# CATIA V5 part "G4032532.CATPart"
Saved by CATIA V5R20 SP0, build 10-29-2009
Part number: G4032532
Revision: 3
Definition: design
Nomenclature: G4032532
Source: made
Description: NOT SPECIFIED
Bounding box of the stored display mesh (mm): x -16 to 16, y -18.807 to 18.807, z -19 to 19
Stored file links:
  C:\Users\Raffaele\Desktop\3D X SITO CF\BOLEX\27-BUSH REF 403\G4032532.CATPart
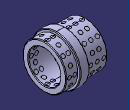
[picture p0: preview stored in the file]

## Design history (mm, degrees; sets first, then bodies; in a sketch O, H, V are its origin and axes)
Body1 "MANIFOLD_SOLID_BREP #9169" (main body)
  Solid1: solid without history
Body2 "MANIFOLD_SOLID_BREP #9312"
  Solid2: solid without history
Body3 "MANIFOLD_SOLID_BREP #9455"
  Solid3: solid without history
Body4 "MANIFOLD_SOLID_BREP #9598"
  Solid4: solid without history
Body5 "MANIFOLD_SOLID_BREP #9741"
  Solid5: solid without history
Body6 "MANIFOLD_SOLID_BREP #9886"
  Solid6: solid without history
Body7 "MANIFOLD_SOLID_BREP #10031"
  Solid7: solid without history
Body8 "MANIFOLD_SOLID_BREP #10176"
  Solid8: solid without history
Body9 "MANIFOLD_SOLID_BREP #10321"
  Solid9: solid without history
Body10 "MANIFOLD_SOLID_BREP #10466"
  Solid10: solid without history
Body11 "MANIFOLD_SOLID_BREP #10611"
  Solid11: solid without history
Body12 "MANIFOLD_SOLID_BREP #10756"
  Solid12: solid without history
Body13 "MANIFOLD_SOLID_BREP #10901"
  Solid13: solid without history
Body14 "MANIFOLD_SOLID_BREP #11046"
  Solid14: solid without history
Body15 "MANIFOLD_SOLID_BREP #11191"
  Solid15: solid without history
Body16 "MANIFOLD_SOLID_BREP #11336"
  Solid16: solid without history
Body17 "MANIFOLD_SOLID_BREP #11481"
  Solid17: solid without history
Body18 "MANIFOLD_SOLID_BREP #11626"
  Solid18: solid without history
Body19 "MANIFOLD_SOLID_BREP #11771"
  Solid19: solid without history
Body20 "MANIFOLD_SOLID_BREP #11916"
  Solid20: solid without history
Body21 "MANIFOLD_SOLID_BREP #12061"
  Solid21: solid without history
Body22 "MANIFOLD_SOLID_BREP #12206"
  Solid22: solid without history
Body23 "MANIFOLD_SOLID_BREP #12351"
  Solid23: solid without history
Body24 "MANIFOLD_SOLID_BREP #12496"
  Solid24: solid without history
Body25 "MANIFOLD_SOLID_BREP #12641"
  Solid25: solid without history
Body26 "MANIFOLD_SOLID_BREP #12786"
  Solid26: solid without history
Body27 "MANIFOLD_SOLID_BREP #12931"
  Solid27: solid without history
Body28 "MANIFOLD_SOLID_BREP #13076"
  Solid28: solid without history
Body29 "MANIFOLD_SOLID_BREP #13221"
  Solid29: solid without history
Body30 "MANIFOLD_SOLID_BREP #13366"
  Solid30: solid without history
Body31 "MANIFOLD_SOLID_BREP #13511"
  Solid31: solid without history
Body32 "MANIFOLD_SOLID_BREP #13654"
  Solid32: solid without history
Body33 "MANIFOLD_SOLID_BREP #13797"
  Solid33: solid without history
Body34 "MANIFOLD_SOLID_BREP #13942"
  Solid34: solid without history
Body35 "MANIFOLD_SOLID_BREP #14087"
  Solid35: solid without history
Body36 "MANIFOLD_SOLID_BREP #14232"
  Solid36: solid without history
Body37 "MANIFOLD_SOLID_BREP #14377"
  Solid37: solid without history
Body38 "MANIFOLD_SOLID_BREP #14522"
  Solid38: solid without history
Body39 "MANIFOLD_SOLID_BREP #14667"
  Solid39: solid without history
Body40 "MANIFOLD_SOLID_BREP #14812"
  Solid40: solid without history
Body41 "MANIFOLD_SOLID_BREP #14957"
  Solid41: solid without history
Body42 "MANIFOLD_SOLID_BREP #15102"
  Solid42: solid without history
Body43 "MANIFOLD_SOLID_BREP #15247"
  Solid43: solid without history
Body44 "MANIFOLD_SOLID_BREP #15392"
  Solid44: solid without history
Body45 "MANIFOLD_SOLID_BREP #15537"
  Solid45: solid without history
Body46 "MANIFOLD_SOLID_BREP #15682"
  Solid46: solid without history
Body47 "MANIFOLD_SOLID_BREP #15827"
  Solid47: solid without history
Body48 "MANIFOLD_SOLID_BREP #15972"
  Solid48: solid without history
Body49 "MANIFOLD_SOLID_BREP #16117"
  Solid49: solid without history
Body50 "MANIFOLD_SOLID_BREP #16262"
  Solid50: solid without history
Body51 "MANIFOLD_SOLID_BREP #16407"
  Solid51: solid without history
Body52 "MANIFOLD_SOLID_BREP #16552"
  Solid52: solid without history
Body53 "MANIFOLD_SOLID_BREP #16697"
  Solid53: solid without history
Body54 "MANIFOLD_SOLID_BREP #16840"
  Solid54: solid without history
Body55 "MANIFOLD_SOLID_BREP #16983"
  Solid55: solid without history
Body56 "MANIFOLD_SOLID_BREP #17126"
  Solid56: solid without history
Body57 "MANIFOLD_SOLID_BREP #17269"
  Solid57: solid without history
Body58 "MANIFOLD_SOLID_BREP #17414"
  Solid58: solid without history
Body59 "MANIFOLD_SOLID_BREP #17559"
  Solid59: solid without history
Body60 "MANIFOLD_SOLID_BREP #17704"
  Solid60: solid without history
Body61 "MANIFOLD_SOLID_BREP #17849"
  Solid61: solid without history
Body62 "MANIFOLD_SOLID_BREP #17994"
  Solid62: solid without history
Body63 "MANIFOLD_SOLID_BREP #18139"
  Solid63: solid without history
Body64 "MANIFOLD_SOLID_BREP #18284"
  Solid64: solid without history
Body65 "MANIFOLD_SOLID_BREP #18429"
  Solid65: solid without history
